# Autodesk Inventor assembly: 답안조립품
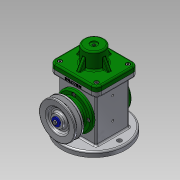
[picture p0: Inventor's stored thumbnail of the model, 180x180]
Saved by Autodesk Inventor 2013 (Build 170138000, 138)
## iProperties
Created: 2018-10
Part Number: 답안조립품
Document SubType Name: Assembly
Designer: Administrator
Author: Administrator
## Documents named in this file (18)
- C:\Documents and Settings\Administrator\바탕 화면\481007V1033\답안조립품.iam
- C:\Documents and Settings\Administrator\바탕 화면\481007V1033\본체.ipt
- C:\Documents and Settings\Administrator\바탕 화면\481007V1033\앞커버.ipt
- C:\Documents and Settings\Administrator\바탕 화면\481007V1033\볼트 M4 x 8.ipt
- C:\Documents and Settings\Administrator\바탕 화면\481007V1033\뒤커버.ipt
- C:\Documents and Settings\Administrator\바탕 화면\481007V1033\편심축.ipt
- C:\Documents and Settings\Administrator\바탕 화면\481007V1033\베어링 17 x 40 x 12.ipt
- C:\Documents and Settings\Administrator\바탕 화면\481007V1033\링크.ipt
- C:\Documents and Settings\Administrator\바탕 화면\481007V1033\슬라이더.ipt
- C:\Documents and Settings\Administrator\바탕 화면\481007V1033\클레비스 핀 6 x 22.ipt
- 클레비스 핀 6 x 22.ipt
- C:\Documents and Settings\Administrator\바탕 화면\481007V1033\덮개.ipt
- C:\Documents and Settings\Administrator\바탕 화면\481007V1033\E-링.ipt
- C:\Documents and Settings\Administrator\바탕 화면\481007V1033\오일 실 17 30 8.ipt
- C:\Documents and Settings\Administrator\바탕 화면\481007V1033\키 4 x 4 x 12.ipt
- C:\Documents and Settings\Administrator\바탕 화면\481007V1033\V-벨트풀리.ipt
- C:\Documents and Settings\Administrator\바탕 화면\481007V1033\와셔 4x16.ipt
- C:\Documents and Settings\Administrator\바탕 화면\481007V1033\볼트 M4 x 10.ipt
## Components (2 placed, 2 different names)
1. E-링:1
2. V-벨트풀리:1 — 각도:1
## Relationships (1: Angle 1)
- 각도:1 [Angle]: V-벨트풀리:1
